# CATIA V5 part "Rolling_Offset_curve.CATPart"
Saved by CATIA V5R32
Part number: Part1
Bounding box of the stored display mesh (mm): x -34.79 to 141.747, y 0 to 36.041, z 0 to 120
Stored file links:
  D:\PROJECTS\Project 2022\CATIA V5 6R 2022\Resources\Part Files\c17_catia_v6_6r2022_prt\Rolling_Offset_curve.CATPart
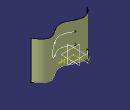
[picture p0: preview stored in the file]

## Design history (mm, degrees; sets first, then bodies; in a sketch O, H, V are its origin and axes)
Set1
  Sketch1 on xy-plane, origin (0, 0, 0), H (1, 0, 0), V (0, 1, 0)
    spline S1 through (141.7471, 7.6193) (96.894, 32.921) (61.2417, 14.2322) (16.9636, 29.4707) (-34.7899, 9.0569)
  Extrude1: Element1 Sketch1, Lim1 120, Lim2 0
  Plane1: type Offset, RefPlane zx-plane, Offset 75
  Sketch2 on Plane1, origin (0, 75, 0), H (-1, 0, 0), V (0, 0, 1)
    line L1 (-21.0945, 87.991) -> (-85.0485, 87.991)
    arc A1 centre (-85.0485, 70.1055) radius 17.8854 from (-85.0485, 87.991) to (-85.0485, 52.2201) ccw
    line L2 (-85.0485, 52.2201) -> (-21.0945, 52.2201)
    horizontal: L1 H
    tangency: A1 L1, L2 A1
  Project1: ToProject Sketch2, Support Extrude1, Direction zx-plane
Body1 (main body)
